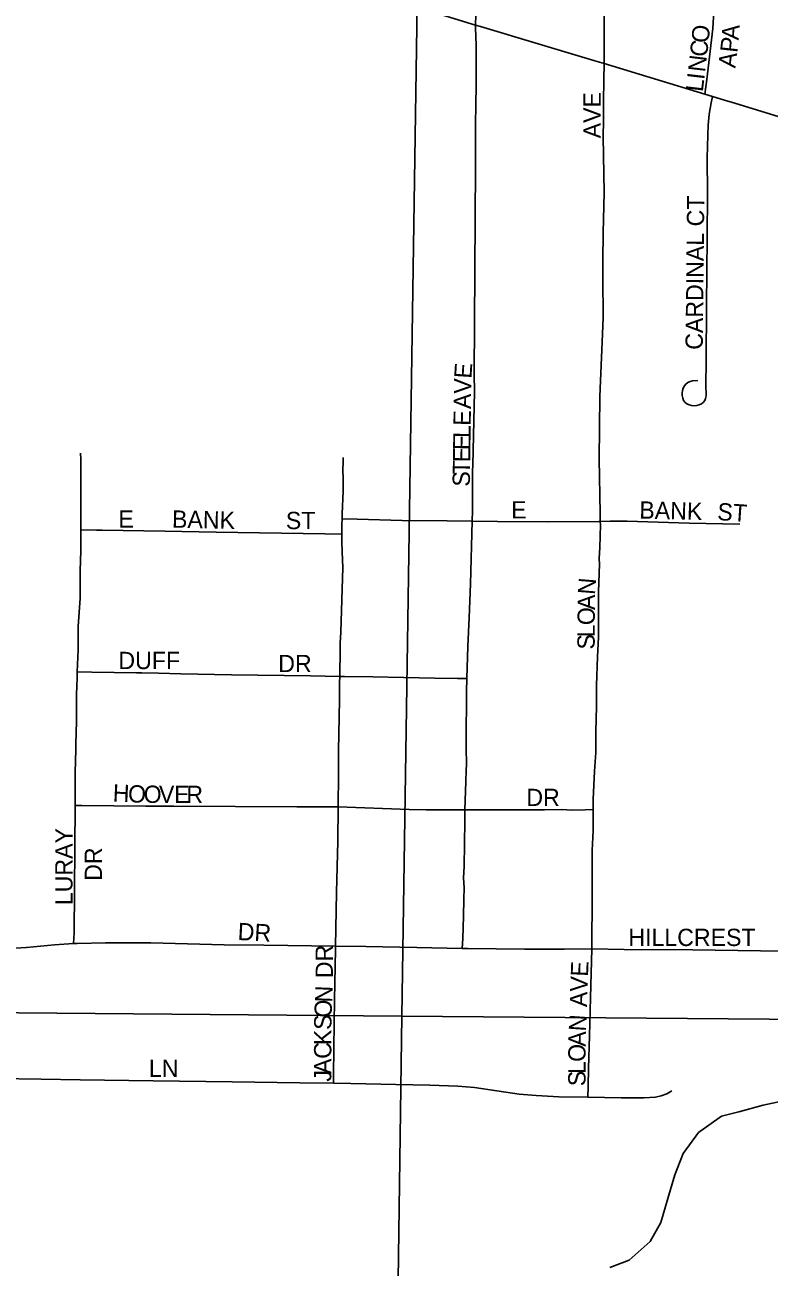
# Model space of a CAD drawing. Extents: x 1874609 to 2204689, y 815661 to 1281160.
# Drawn here: x 2023217 to 2025368, y 1040325 to 1043918 of the extents above; entities that cross this region are included whole.
import ezdxf

# ---------------------------------------------------------------- set-up
doc = ezdxf.new("R2010")
doc.units = 0
for name, color, linetype in [('GM_X_City_Street', 7, 'Continuous'), ('GM_X_City_Street_Text', 7, 'Continuous'), ('GM_X_Minor_River', 7, 'Continuous'), ('GM_X_Section', 7, 'Continuous'), ('GM_X_State_Route', 7, 'Continuous')]:
    doc.layers.add(name, color=color, linetype=linetype)

msp = doc.modelspace()

# ---------------------------------------------------------------- linework, layer by layer
at = {"layer": 'GM_X_City_Street'}
for points in [[(2024891.4, 1043805.5), (2024891.4, 1043814.6), (2024891.6, 1043901.1), (2024892.7, 1044015.4), (2024893.9, 1044129.2), (2024896.3, 1044275.2), (2024898.9, 1044521.7), (2024899.4, 1044584.7)], [(2025183, 1043716.8), (2025188.2, 1043759.9), (2025206, 1043907.4), (2025208.9, 1043956.8), (2025208.9, 1044006.2), (2025206.1, 1044038), (2025202.4, 1044088.3), (2025201, 1044187.2), (2025205.1, 1044434.8), (2025204.6, 1044451.3), (2025202.3, 1044467.6), (2025198.3, 1044483.6), (2025187.7, 1044514.9), (2025175.5, 1044545.7), (2025166.9, 1044559.8), (2025154.7, 1044570.3), (2025139.5, 1044576.2), (2025123.2, 1044578.8), (2025057.2, 1044583.6), (2024941.7, 1044584.4), (2024917.7, 1044584.6), (2024899.4, 1044584.7)], [(2024519.9, 1043917), (2024521.5, 1043976.9)], [(2024510.3, 1042482.3), (2024511.2, 1042513.4), (2024511.3, 1042627.9), (2024512.3, 1042644.3), (2024516.3, 1042857.2), (2024515.8, 1042906.6), (2024520, 1043507), (2024520.1, 1043572.8), (2024519.9, 1043633.8), (2024520.6, 1043682.8), (2024521.4, 1043746.8), (2024521.2, 1043796), (2024521.5, 1043857.8), (2024520.1, 1043908.9), (2024519.9, 1043917)], [(2024880.3, 1042481.1), (2024879.7, 1042504.6), (2024877.3, 1042662.8), (2024879.5, 1042842.9), (2024886.4, 1043022.9), (2024888.9, 1043071.3), (2024887.5, 1043186.6), (2024887.7, 1043219), (2024887.8, 1043235.4), (2024888.6, 1043317.3), (2024891.3, 1043431.7), (2024889, 1043595), (2024889.5, 1043639.7), (2024889.5, 1043694.7), (2024890.7, 1043758.2), (2024891.4, 1043805.5)], [(2025162.2, 1042888.9), (2025146.8, 1042888.2), (2025139.7, 1042886.5), (2025133.2, 1042883.4), (2025127.6, 1042878.8), (2025123.3, 1042873.7), (2025119.8, 1042866.7), (2025117.9, 1042860.1), (2025117.2, 1042852), (2025117.1, 1042845.2), (2025118.5, 1042837.8), (2025120.9, 1042831.4), (2025125.8, 1042825.8), (2025130.5, 1042821.8), (2025137.5, 1042818.5), (2025144.1, 1042817.1), (2025151.7, 1042815.9), (2025159, 1042816.5), (2025166.4, 1042818.5), (2025172.5, 1042821.4), (2025178, 1042825.8), (2025182.1, 1042831.1), (2025184.9, 1042836.5), (2025186.2, 1042844.7), (2025185.8, 1042877), (2025186.4, 1042943.1), (2025186.9, 1043105.7), (2025189.5, 1043302.9), (2025190.3, 1043429.6), (2025189.2, 1043533), (2025191.2, 1043598.4), (2025192, 1043626.9), (2025195, 1043659.3), (2025200.9, 1043691.7), (2025204.3, 1043710.4)], [(2023379.1, 1042457.5), (2023379.1, 1042503.4), (2023379.1, 1042594.5), (2023378.8, 1042661.3), (2023378.2, 1042678.5)], [(2024134.2, 1042489), (2024134.5, 1042503.7), (2024137.1, 1042569.3), (2024137.6, 1042601.7), (2024136.6, 1042633.3), (2024137, 1042649.7), (2024137, 1042665.9)], [(2024133.6, 1042444.5), (2024133.6, 1042455), (2024133.7, 1042471.1), (2024134.2, 1042489)], [(2024134.2, 1042489), (2024177.5, 1042487.9), (2024307.9, 1042484.5), (2024437.5, 1042483), (2024510.3, 1042482.3)], [(2023368.1, 1042046.6), (2023371.2, 1042110.4), (2023371.2, 1042178.1), (2023376.5, 1042258.8), (2023376.5, 1042339.5), (2023379.1, 1042396.7), (2023379.1, 1042457.5)], [(2023379.1, 1042457.5), (2023424.3, 1042456.5), (2023440.8, 1042456.1), (2023621.9, 1042453.3), (2023770.4, 1042450.8), (2024083.7, 1042445.3), (2024133.6, 1042444.5)], [(2024495, 1042027.3), (2024497.2, 1042120.8), (2024501.4, 1042202.4), (2024505, 1042300.6), (2024510.3, 1042482.3)], [(2024510.3, 1042482.3), (2024583.4, 1042481.6), (2024729.8, 1042480.7), (2024876.4, 1042481), (2024880.3, 1042481.1)], [(2024859.7, 1041647.9), (2024859.7, 1041678.4), (2024864, 1041759.3), (2024867.7, 1041813.3), (2024867.7, 1041873), (2024869.5, 1041947.5), (2024869.6, 1042007.2), (2024872.7, 1042089.5), (2024875.3, 1042146.8), (2024875.3, 1042204), (2024875.2, 1042277.6), (2024877.8, 1042358.2), (2024877.6, 1042374.6), (2024878.6, 1042406.4), (2024880.6, 1042471.7), (2024880.3, 1042481.1)], [(2024880.3, 1042481.1), (2024908.8, 1042482.1), (2024957.6, 1042482.2), (2025136.9, 1042476.3), (2025283.4, 1042473.4)], [(2024127.1, 1042033), (2024128.2, 1042112.9), (2024128.7, 1042129.1), (2024130.1, 1042161.2), (2024136.2, 1042347.9), (2024134.7, 1042393.5), (2024133.6, 1042423.6), (2024133.5, 1042439.2), (2024133.6, 1042444.5)], [(2023362.2, 1041660), (2023362.3, 1041764.3), (2023363.5, 1041780.5), (2023365.4, 1041878.6), (2023366.4, 1041894.7), (2023366.3, 1041976.7), (2023367.6, 1042009.2), (2023367.9, 1042024.6), (2023368.1, 1042046.6)], [(2023368.1, 1042046.6), (2023410.8, 1042045.9), (2023540, 1042043.8), (2023555.5, 1042043.9), (2023603.1, 1042042.8), (2023667.7, 1042041.1), (2023814.5, 1042038.2), (2024042.7, 1042034.5), (2024127.1, 1042033)], [(2024122.4, 1041655.9), (2024122.4, 1041670.6), (2024123.4, 1041736.1), (2024124.1, 1041818.2), (2024126.1, 1041965.8), (2024126.8, 1042014.7), (2024127.1, 1042033)], [(2024127.1, 1042033), (2024140.7, 1042032.8), (2024222.6, 1042031.6), (2024402.4, 1042027.8), (2024467.9, 1042027.5), (2024495, 1042027.3)], [(2024489.3, 1041647.3), (2024491.3, 1041729.2), (2024492.7, 1041762), (2024493.2, 1041778.4), (2024493.2, 1041794.7), (2024492.7, 1041810.4), (2024492.6, 1041826.5), (2024492.4, 1041842.9), (2024492.8, 1041891.8), (2024493.6, 1041940.9), (2024494, 1041990), (2024495, 1042027.3)], [(2023358.1, 1041260.5), (2023359.3, 1041292.1), (2023362.2, 1041660)], [(2023362.2, 1041660), (2023381.6, 1041660.3), (2023566.4, 1041658.4), (2023647.7, 1041657.9), (2024003.1, 1041656.4), (2024084.2, 1041655.9), (2024116.7, 1041656.1), (2024122.4, 1041655.9)], [(2024115.4, 1041253.3), (2024118.3, 1041408.4), (2024122.1, 1041556.3), (2024122.4, 1041655.9)], [(2024122.4, 1041655.9), (2024328.3, 1041648.4), (2024376.7, 1041647.8), (2024489.3, 1041647.3)], [(2024481.6, 1041246.5), (2024483.2, 1041274.8), (2024485.4, 1041339.8), (2024486.2, 1041388.8), (2024487.2, 1041422.1), (2024485.4, 1041450.9), (2024486.3, 1041467.1), (2024486.9, 1041483.9), (2024488.5, 1041614.6), (2024489.3, 1041647.3)], [(2024489.3, 1041647.3), (2024506.6, 1041647.2), (2024589.1, 1041647.2), (2024661.9, 1041647.2), (2024719.1, 1041647.2), (2024767.3, 1041648.3), (2024799.7, 1041646), (2024836.3, 1041647.1), (2024859.7, 1041647.9)], [(2024855.9, 1041245.3), (2024857.1, 1041402.5), (2024857.1, 1041436.4), (2024857.1, 1041530), (2024859.7, 1041587.3), (2024859.7, 1041647.9)], [(2023358.1, 1041260.5), (2023368.3, 1041261.3), (2023449.9, 1041263), (2023580.8, 1041262.3), (2023793.6, 1041257.1), (2023908.3, 1041255.7), (2024115.4, 1041253.3)], [(2022991, 1041249.3), (2022993.3, 1041249.3), (2023042.1, 1041247.2), (2023074.7, 1041245.3), (2023123.5, 1041244.7), (2023172.7, 1041245.9), (2023221.8, 1041249), (2023303.2, 1041256.7), (2023358.1, 1041260.5)], [(2024109.5, 1040856.6), (2024109.5, 1040880.9), (2024111.1, 1041031.3), (2024112.1, 1041097.1), (2024115.2, 1041244.1), (2024115.4, 1041253.3)], [(2024115.4, 1041253.3), (2024203, 1041252.3), (2024350.3, 1041248.9), (2024481.6, 1041246.5)], [(2024481.6, 1041246.5), (2024497.7, 1041246.2), (2024661.2, 1041244.6), (2024775.8, 1041244.5), (2024855.9, 1041245.3)], [(2024844, 1040816.1), (2024845, 1040848.5), (2024846.4, 1040899.5), (2024849.2, 1040994), (2024851.8, 1041103.3), (2024855.9, 1041245.3)], [(2024855.9, 1041245.3), (2024949.5, 1041243.2), (2025146.6, 1041242.4), (2025277.9, 1041240.1), (2025409.4, 1041238.5), (2025524.3, 1041236.4), (2025589.6, 1041232.8), (2025621.9, 1041229.2), (2025669.7, 1041219.5), (2025701.1, 1041210.8), (2025747.4, 1041194.8), (2025792.5, 1041176), (2025836.2, 1041154), (2025864.3, 1041137.6), (2025891.2, 1041119.3), (2025916.8, 1041099.5), (2025993.2, 1041029.5)], [(2022676.5, 1040906), (2022697, 1040905.7), (2022794.1, 1040904.1), (2022858.7, 1040899.6), (2022939.4, 1040889.7), (2023020.5, 1040879), (2023069.3, 1040873.8), (2023134.7, 1040870.5), (2023264.4, 1040868.4), (2023377.4, 1040866.9), (2023588.3, 1040863.8), (2023815.9, 1040860.3), (2024012, 1040857.4), (2024109.5, 1040856.6)], [(2024109.5, 1040856.6), (2024159, 1040856.3), (2024289.4, 1040853.4), (2024387.2, 1040851.6), (2024468.6, 1040848.7), (2024517.1, 1040844.4), (2024581.4, 1040834.5), (2024646.3, 1040825.2), (2024695.4, 1040820.8), (2024760.9, 1040817.6), (2024844, 1040816.1)], [(2024844, 1040816.1), (2024940.9, 1040814.4), (2025006.6, 1040814.6), (2025039.7, 1040816.7), (2025056.3, 1040819.9), (2025072.4, 1040826), (2025087.2, 1040835)]]:
    msp.add_lwpolyline(points, dxfattribs=at)
at = {"layer": 'GM_X_Minor_River'}
msp.add_lwpolyline([(2025419, 1040807.4), (2025350.7, 1040793.6), (2025280.5, 1040773.8), (2025230.3, 1040761.9), (2025164, 1040713.9), (2025119.7, 1040653.9), (2025095.4, 1040591.8), (2025075.2, 1040523.6), (2025054.9, 1040453.5), (2025024.7, 1040399.4), (2024964.3, 1040345.4), (2024908.1, 1040323.6)], dxfattribs=at)
at = {"layer": 'GM_X_Section'}
for points in [[(2024387.7, 1046393.6), (2024307, 1041050.6), (2018988, 1041097.3), (2019020.7, 1046448.2)], [(2029702.7, 1046322.8), (2029613.9, 1041007.7), (2024307, 1041050.6), (2024387.7, 1046393.6)], [(2018988, 1041097.3), (2024307, 1041050.6), (2024232.1, 1035713.6), (2018912.9, 1035910.5)], [(2024307, 1041050.6), (2029613.9, 1041007.7), (2029549.1, 1035652.8), (2024232.1, 1035713.6)]]:
    msp.add_lwpolyline(points, close=True, dxfattribs=at)
at = {"layer": 'GM_X_State_Route'}
for points in [[(2023657, 1044177.1), (2023781.6, 1044139.7), (2023894.2, 1044105.9), (2024064.4, 1044054.8), (2024187.8, 1044017.7), (2024362.9, 1043965.1), (2024519.9, 1043917), (2024534.6, 1043912.5), (2024691.6, 1043865.2), (2024864.4, 1043813.7), (2024891.4, 1043805.5), (2025183, 1043716.8), (2025204.3, 1043710.4), (2025239.7, 1043699.6)], [(2025239.7, 1043699.6), (2025268.8, 1043690.8), (2025409.8, 1043648.1), (2025655.6, 1043573.1), (2025801.6, 1043528.5), (2025884.2, 1043503.4), (2026335.3, 1043366.3), (2026633.6, 1043275.9), (2026752.6, 1043240.2), (2026776.3, 1043233.1)]]:
    msp.add_lwpolyline(points, dxfattribs=at)

# ---------------------------------------------------------------- texts
at = {"layer": 'GM_X_City_Street_Text'}
for s, rotation, p in [('O', 84.6207, (2025193.2, 1043863.6)), ('A', 85.6348, (2025280.2, 1043872.2)), ('C', 83.2575, (2025188.4, 1043822.9)), ('P', 83.854, (2025276.3, 1043835.5)), ('N', 83.2736, (2025183.3, 1043779.2)), ('A', 82.9454, (2025270.7, 1043791)), ('L', 83.2646, (2025176.6, 1043722.4)), ('I', 83.2784, (2025180.7, 1043757.4)), ('AVE', 90, (2024881.7, 1043589.3)), ('CARDINAL CT', 89.3914, (2025176.5, 1042977.6)), ('E', 86.4731, (2024507.8, 1042893.6)), ('V', 89.0601, (2024507.1, 1042850.2)), ('A', 89.1934, (2024506.5, 1042806.2)), ('E', 89.2077, (2024505.8, 1042757.8)), ('L', 89.2047, (2024505.3, 1042722.6)), ('E', 89.2047, (2024504.8, 1042687.4)), ('E', 89.1804, (2024504.3, 1042652.2)), ('T', 89.1911, (2024503.8, 1042617)), ('S', 89.2077, (2024503.3, 1042581.8)), ('E', 0, (2024622.7, 1042489.9)), ('BANK', 358.5316, (2024992.7, 1042489.9)), ('ST', 356.1879, (2025217.4, 1042485.5)), ('E', 0, (2023487.5, 1042463.5)), ('BANK', 358.8318, (2023642, 1042463.5)), ('ST', 0, (2023971.5, 1042459.1)), ('N', 85.4052, (2024864.8, 1042268.2)), ('A', 89.7158, (2024864.7, 1042225.2)), ('O', 89.7377, (2024864.5, 1042181.3)), ('L', 89.7441, (2024864.3, 1042146.1)), ('S', 89.7268, (2024864.1, 1042110.8)), ('DUFF', 0, (2023487.5, 1042054.3)), ('DR', 0, (2023949.5, 1042045.5)), ('H', 357.4421, (2023470.4, 1041671.5)), ('O', 357.6284, (2023514.5, 1041669.5)), ('O', 359.2945, (2023560.1, 1041667.7)), ('V', 359.9703, (2023604.7, 1041667.1)), ('E', 359.9956, (2023648.7, 1041667.1)), ('R', 359.9941, (2023683.9, 1041667.1)), ('DR', 0, (2024666.7, 1041658.3)), ('LURAY', 90, (2023354.9, 1041371.7)), ('DR', 90, (2023440, 1041442.1)), ('DR', 356.8215, (2023831.3, 1041271.1)), ('HILLCREST', 0, (2024961.5, 1041253.5)), ('DR', 90, (2024107.4, 1041160.5)), ('E', 87.5947, (2024844.7, 1041164.3)), ('V', 87.7915, (2024843, 1041120.4)), ('N', 87.7041, (2024105.2, 1041089.5)), ('A', 88.9071, (2024842.1, 1041076.7)), ('O', 87.8579, (2024103.5, 1041045.6)), ('S', 89.0711, (2024103, 1041010.7)), ('N', 86.2164, (2024838.8, 1041005.6)), ('K', 89.9703, (2024103, 1040966.9)), ('A', 88.6449, (2024837.8, 1040962.2)), ('C', 89.9757, (2024103, 1040927.3)), ('O', 89.9703, (2024837.8, 1040918.5)), ('LN', 0, (2023575.5, 1040875.1)), ('A', 89.9781, (2024102.9, 1040883.3)), ('L', 89.9453, (2024837.8, 1040883.3)), ('J', 90, (2024102.9, 1040861.3)), ('S', 89.9727, (2024837.7, 1040848.1))]:
    msp.add_text(s, height=50, rotation=rotation, dxfattribs=at).set_placement(p)

doc.saveas('drawing.dxf')
